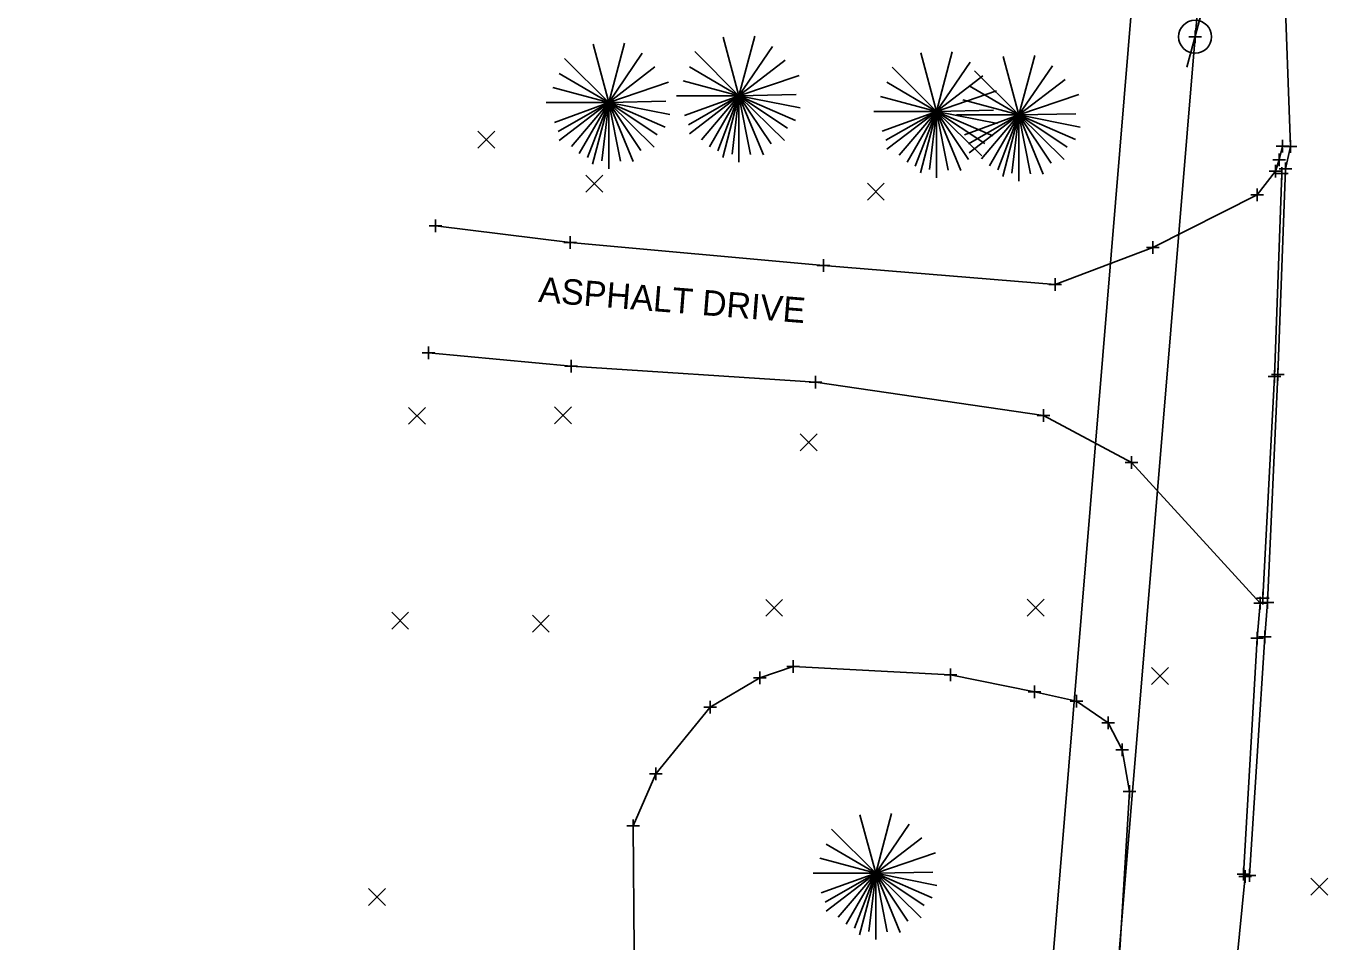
# Model space of a CAD drawing. Extents: x 1380440 to 1381945, y 468756 to 470369.
# Drawn here: x 1381467.5 to 1381570.5, y 469686 to 469758.2 of the extents above; entities that cross this region are included whole.
import ezdxf

# ---------------------------------------------------------------- set-up
doc = ezdxf.new("R2010")
doc.units = 0
for name, color, linetype in [('DR_P_Storm_Sewer', 7, 'Continuous'), ('DR_X_Cells', 7, 'Continuous'), ('GE_P_Driveway_CL', 7, 'Continuous'), ('PV_X_COP', 7, 'Continuous'), ('RW_P_Esmt_TMP', 7, 'Continuous'), ('RW_X_Esmt_SH', 7, 'Continuous'), ('SC_Scratch10', 7, 'Continuous'), ('SH_Named_Boundary', 7, 'Continuous'), ('UT_X_Gas', 7, 'Continuous'), ('UT_X_Overhead_Combined', 7, 'Continuous'), ('X-SUBDIVISION', 7, 'Continuous')]:
    doc.layers.add(name, color=color, linetype=linetype)

msp = doc.modelspace()

# ---------------------------------------------------------------- linework, layer by layer
at = {"layer": 'DR_P_Storm_Sewer'}
msp.add_lwpolyline([(1381553.61, 469681.87), (1381554.59, 469697.85), (1381554.02, 469701.13), (1381552.9, 469703.26), (1381550.42, 469704.97), (1381547.1, 469705.7), (1381540.46, 469707.05), (1381528.05, 469707.71), (1381525.41, 469706.81), (1381521.51, 469704.5), (1381517.2, 469699.24), (1381515.42, 469695.13), (1381515.51, 469685.3), (1381518.45, 469671.91), (1381521.91, 469663.58), (1381525.51, 469660.65), (1381530.1, 469658.77), (1381537.53, 469659.25), (1381542.81, 469659.47), (1381547.18, 469661.79), (1381552.24, 469676.73)], close=True, dxfattribs=at)
at = {"layer": 'DR_X_Cells'}
for points in [[(1381566.66, 469748.77), (1381566.42, 469747.7), (1381566.12, 469746.81)], [(1381564.9, 469712.7), (1381564.68, 469709.94), (1381563.59, 469691.32)]]:
    msp.add_lwpolyline(points, dxfattribs=at)
at = {"layer": 'GE_P_Driveway_CL'}
for p, q in [((1381503.17, 469748.62), (1381504.5, 469749.95)), ((1381503.17, 469749.95), (1381504.5, 469748.62)), ((1381511.69, 469745.13), (1381513.02, 469746.47)), ((1381511.69, 469746.47), (1381513.02, 469745.13)), ((1381533.91, 469744.5), (1381535.24, 469745.84)), ((1381533.91, 469745.84), (1381535.24, 469744.5)), ((1381497.68, 469726.82), (1381499.02, 469728.15)), ((1381497.68, 469728.15), (1381499.02, 469726.82)), ((1381509.22, 469726.87), (1381510.55, 469728.2)), ((1381509.22, 469728.2), (1381510.55, 469726.87)), ((1381528.6, 469724.74), (1381529.94, 469726.07)), ((1381528.6, 469726.07), (1381529.94, 469724.74)), ((1381525.88, 469711.67), (1381527.21, 469713)), ((1381525.88, 469713), (1381527.21, 469711.67)), ((1381546.53, 469711.69), (1381547.86, 469713.03)), ((1381546.53, 469713.03), (1381547.86, 469711.69)), ((1381496.37, 469710.66), (1381497.7, 469711.99)), ((1381496.37, 469711.99), (1381497.7, 469710.66)), ((1381507.47, 469710.43), (1381508.8, 469711.77)), ((1381507.47, 469711.77), (1381508.8, 469710.43)), ((1381556.34, 469706.3), (1381557.67, 469707.64)), ((1381556.34, 469707.64), (1381557.67, 469706.3)), ((1381494.53, 469688.85), (1381495.87, 469690.18)), ((1381494.53, 469690.18), (1381495.87, 469688.85)), ((1381568.91, 469689.67), (1381570.25, 469691.01)), ((1381568.91, 469691.01), (1381570.25, 469689.67))]:
    msp.add_line(p, q, dxfattribs=at)
at = {"layer": 'PV_X_COP'}
msp.add_line((1381560.74, 469761.01), (1381559.13, 469755.01), dxfattribs=at)
msp.add_circle((1381559.77, 469757.41), 1.3, dxfattribs=at)
at = {"layer": 'RW_P_Esmt_TMP'}
msp.add_lwpolyline([(1381504.03, 469796.45), (1381535.81, 469794.23), (1381542.35, 469793.56), (1381553.91, 469786.69), (1381557.54, 469783.33), (1381558.31, 469783.03), (1381558.93, 469783.94), (1381560.15, 469782.7), (1381561.95, 469780.57), (1381562.88, 469779.33), (1381563.72, 469777.65), (1381566.46, 469770.89), (1381567.07, 469765.6), (1381567.32, 469762.48), (1381566.8, 469762.44), (1381567.31, 469748.74), (1381566.9, 469746.97), (1381566.29, 469730.74), (1381565.48, 469712.75), (1381565.27, 469710.06), (1381564.07, 469691.21), (1381563.72, 469691.13), (1381563.05, 469684.22)], dxfattribs=at)
at = {"layer": 'RW_X_Esmt_SH'}
for points in [[(1381566.12, 469746.81), (1381564.67, 469744.93), (1381556.43, 469740.78), (1381548.72, 469737.86), (1381530.45, 469739.35), (1381510.46, 469741.16), (1381499.82, 469742.49)], [(1381566.61, 469746.61), (1381566.05, 469730.59), (1381565.13, 469713.09)], [(1381499.26, 469732.46), (1381510.53, 469731.41), (1381529.82, 469730.14), (1381547.8, 469727.52), (1381554.75, 469723.81), (1381564.9, 469712.7)]]:
    msp.add_lwpolyline(points, dxfattribs=at)
at = {"layer": 'SC_Scratch10'}
for p, q in [((1381523.77, 469752.75), (1381522.53, 469757.36)), ((1381523.77, 469752.75), (1381525.03, 469757.44)), ((1381513.49, 469752.21), (1381512.25, 469756.83)), ((1381513.49, 469752.21), (1381514.74, 469756.91)), ((1381513.49, 469752.21), (1381516.14, 469756.1)), ((1381523.77, 469752.75), (1381520.28, 469756.23)), ((1381523.77, 469752.75), (1381526.42, 469756.63)), ((1381539.35, 469751.52), (1381538.12, 469756.13)), ((1381539.35, 469751.52), (1381540.61, 469756.22)), ((1381545.86, 469751.24), (1381547.12, 469755.93)), ((1381513.49, 469752.21), (1381510, 469755.7)), ((1381513.49, 469752.21), (1381517.14, 469755.02)), ((1381523.77, 469752.75), (1381519.86, 469755.04)), ((1381523.77, 469752.75), (1381527.43, 469755.55)), ((1381539.35, 469751.52), (1381535.86, 469755.01)), ((1381539.35, 469751.52), (1381542.01, 469755.41)), ((1381545.86, 469751.24), (1381544.62, 469755.85)), ((1381545.86, 469751.24), (1381548.51, 469755.12)), ((1381513.49, 469752.21), (1381509.58, 469754.51)), ((1381523.77, 469752.75), (1381519.36, 469753.93)), ((1381523.77, 469752.75), (1381528.51, 469754.35)), ((1381539.35, 469751.52), (1381543.01, 469754.33)), ((1381545.86, 469751.24), (1381542.37, 469754.72)), ((1381545.86, 469751.24), (1381549.52, 469754.04)), ((1381513.49, 469752.21), (1381509.07, 469753.4)), ((1381513.49, 469752.21), (1381518.22, 469753.82)), ((1381523.77, 469752.75), (1381528.28, 469752.84)), ((1381539.35, 469751.52), (1381535.45, 469753.82)), ((1381539.35, 469751.52), (1381544.09, 469753.13)), ((1381545.86, 469751.24), (1381541.95, 469753.53)), ((1381545.86, 469751.24), (1381550.6, 469752.84)), ((1381508.55, 469752.21), (1381513.49, 469752.21)), ((1381513.49, 469752.21), (1381509.2, 469750.65)), ((1381513.49, 469752.21), (1381509.5, 469749.93)), ((1381513.49, 469752.21), (1381509.58, 469749.22)), ((1381513.49, 469752.21), (1381510.54, 469748.75)), ((1381513.49, 469752.21), (1381511.17, 469748.2)), ((1381513.49, 469752.21), (1381511.82, 469747.87)), ((1381513.49, 469752.21), (1381512.22, 469747.36)), ((1381513.49, 469752.21), (1381512.95, 469747.62)), ((1381513.49, 469752.21), (1381518, 469752.31)), ((1381513.49, 469746.97), (1381513.49, 469752.21)), ((1381513.49, 469752.21), (1381514.41, 469747.58)), ((1381513.49, 469752.21), (1381515.42, 469747.55)), ((1381513.49, 469752.21), (1381516.02, 469748.42)), ((1381513.49, 469752.21), (1381517.08, 469748.69)), ((1381513.49, 469752.21), (1381517.31, 469749.66)), ((1381513.49, 469752.21), (1381517.95, 469750.27)), ((1381513.49, 469752.21), (1381518.32, 469751.26)), ((1381518.83, 469752.75), (1381523.77, 469752.75)), ((1381523.77, 469752.75), (1381519.48, 469751.18)), ((1381523.77, 469752.75), (1381519.79, 469750.46)), ((1381523.77, 469752.75), (1381519.86, 469749.75)), ((1381523.77, 469752.75), (1381520.82, 469749.28)), ((1381523.77, 469752.75), (1381521.45, 469748.73)), ((1381523.77, 469752.75), (1381522.1, 469748.41)), ((1381523.77, 469752.75), (1381522.51, 469747.89)), ((1381523.77, 469752.75), (1381523.23, 469748.15)), ((1381523.77, 469747.51), (1381523.77, 469752.75)), ((1381523.77, 469752.75), (1381524.69, 469748.11)), ((1381523.77, 469752.75), (1381525.7, 469748.08)), ((1381523.77, 469752.75), (1381526.31, 469748.95)), ((1381523.77, 469752.75), (1381527.36, 469749.22)), ((1381523.77, 469752.75), (1381527.59, 469750.19)), ((1381523.77, 469752.75), (1381528.23, 469750.8)), ((1381523.77, 469752.75), (1381528.6, 469751.79)), ((1381539.35, 469751.52), (1381534.94, 469752.7)), ((1381545.86, 469751.24), (1381541.45, 469752.42)), ((1381534.42, 469751.52), (1381539.35, 469751.52)), ((1381539.35, 469751.52), (1381535.06, 469749.96)), ((1381539.35, 469751.52), (1381535.37, 469749.24)), ((1381539.35, 469751.52), (1381535.45, 469748.53)), ((1381539.35, 469751.52), (1381536.41, 469748.05)), ((1381539.35, 469751.52), (1381537.04, 469747.51)), ((1381539.35, 469751.52), (1381537.69, 469747.18)), ((1381539.35, 469751.52), (1381538.09, 469746.66)), ((1381539.35, 469751.52), (1381538.81, 469746.93)), ((1381539.35, 469751.52), (1381543.86, 469751.61)), ((1381539.35, 469746.28), (1381539.35, 469751.52)), ((1381539.35, 469751.52), (1381540.28, 469746.88)), ((1381539.35, 469751.52), (1381541.29, 469746.85)), ((1381539.35, 469751.52), (1381541.89, 469747.73)), ((1381539.35, 469751.52), (1381542.94, 469748)), ((1381539.35, 469751.52), (1381543.18, 469748.97)), ((1381539.35, 469751.52), (1381543.82, 469749.58)), ((1381539.35, 469751.52), (1381544.18, 469750.56)), ((1381540.93, 469751.24), (1381545.86, 469751.24)), ((1381545.86, 469751.24), (1381541.57, 469749.67)), ((1381545.86, 469751.24), (1381541.88, 469748.95)), ((1381545.86, 469751.24), (1381541.95, 469748.24)), ((1381545.86, 469751.24), (1381542.92, 469747.77)), ((1381545.86, 469751.24), (1381543.54, 469747.22)), ((1381545.86, 469751.24), (1381544.2, 469746.9)), ((1381545.86, 469751.24), (1381544.6, 469746.38)), ((1381545.86, 469751.24), (1381545.32, 469746.64)), ((1381545.86, 469751.24), (1381550.37, 469751.33)), ((1381545.86, 469746), (1381545.86, 469751.24)), ((1381545.86, 469751.24), (1381546.78, 469746.6)), ((1381545.86, 469751.24), (1381547.79, 469746.57)), ((1381545.86, 469751.24), (1381548.4, 469747.44)), ((1381545.86, 469751.24), (1381549.45, 469747.71)), ((1381545.86, 469751.24), (1381549.68, 469748.68)), ((1381545.86, 469751.24), (1381550.32, 469749.29)), ((1381545.86, 469751.24), (1381550.69, 469750.28)), ((1381534.56, 469691.4), (1381533.32, 469696.01)), ((1381534.56, 469691.4), (1381535.81, 469696.1)), ((1381534.56, 469691.4), (1381537.21, 469695.28)), ((1381534.56, 469691.4), (1381531.07, 469694.88)), ((1381534.56, 469691.4), (1381538.21, 469694.2)), ((1381534.56, 469691.4), (1381530.65, 469693.69)), ((1381534.56, 469691.4), (1381530.14, 469692.58)), ((1381534.56, 469691.4), (1381539.29, 469693)), ((1381529.62, 469691.4), (1381534.56, 469691.4)), ((1381534.56, 469691.4), (1381530.27, 469689.84)), ((1381534.56, 469691.4), (1381530.57, 469689.12)), ((1381534.56, 469691.4), (1381530.65, 469688.4)), ((1381534.56, 469691.4), (1381531.61, 469687.93)), ((1381534.56, 469691.4), (1381532.24, 469687.38)), ((1381534.56, 469691.4), (1381532.89, 469687.06)), ((1381534.56, 469691.4), (1381533.29, 469686.54)), ((1381534.56, 469691.4), (1381534.01, 469686.81)), ((1381534.56, 469691.4), (1381539.07, 469691.49)), ((1381534.56, 469686.16), (1381534.56, 469691.4)), ((1381534.56, 469691.4), (1381535.48, 469686.76)), ((1381534.56, 469691.4), (1381536.49, 469686.73)), ((1381534.56, 469691.4), (1381537.09, 469687.6)), ((1381534.56, 469691.4), (1381538.14, 469687.88)), ((1381534.56, 469691.4), (1381538.38, 469688.84)), ((1381534.56, 469691.4), (1381539.02, 469689.46)), ((1381534.56, 469691.4), (1381539.38, 469690.44))]:
    msp.add_line(p, q, dxfattribs=at)
at = {"layer": 'SH_Named_Boundary'}
for p, q in [((1381559.27, 469757.41), (1381560.27, 469757.41)), ((1381559.27, 469757.41), (1381560.27, 469757.41)), ((1381559.77, 469757.91), (1381559.77, 469756.91)), ((1381559.77, 469757.91), (1381559.77, 469756.91)), ((1381559.77, 469757.41), (1381559.77, 469757.41)), ((1381559.77, 469757.41), (1381559.77, 469757.41)), ((1381566.16, 469748.77), (1381567.16, 469748.77)), ((1381566.66, 469749.27), (1381566.66, 469748.27)), ((1381566.66, 469748.77), (1381566.66, 469748.77)), ((1381566.81, 469748.74), (1381567.81, 469748.74)), ((1381567.31, 469749.24), (1381567.31, 469748.24)), ((1381567.31, 469748.74), (1381567.31, 469748.74)), ((1381565.92, 469747.7), (1381566.92, 469747.7)), ((1381566.42, 469748.2), (1381566.42, 469747.2)), ((1381566.42, 469747.7), (1381566.42, 469747.7)), ((1381565.62, 469746.81), (1381566.62, 469746.81)), ((1381565.62, 469746.81), (1381566.62, 469746.81)), ((1381566.12, 469747.31), (1381566.12, 469746.31)), ((1381566.12, 469747.31), (1381566.12, 469746.31)), ((1381566.12, 469746.81), (1381566.12, 469746.81)), ((1381566.12, 469746.81), (1381566.12, 469746.81)), ((1381566.4, 469746.97), (1381567.4, 469746.97)), ((1381566.61, 469747.11), (1381566.61, 469746.11)), ((1381566.9, 469747.47), (1381566.9, 469746.47)), ((1381566.9, 469746.97), (1381566.9, 469746.97)), ((1381566.11, 469746.61), (1381567.11, 469746.61)), ((1381566.61, 469746.61), (1381566.61, 469746.61)), ((1381564.17, 469744.93), (1381565.17, 469744.93)), ((1381564.17, 469744.93), (1381565.17, 469744.93)), ((1381564.67, 469745.43), (1381564.67, 469744.43)), ((1381564.67, 469745.43), (1381564.67, 469744.43)), ((1381564.67, 469744.93), (1381564.67, 469744.93)), ((1381564.67, 469744.93), (1381564.67, 469744.93)), ((1381499.82, 469742.99), (1381499.82, 469741.99)), ((1381499.32, 469742.49), (1381500.32, 469742.49)), ((1381499.82, 469742.49), (1381499.82, 469742.49)), ((1381510.46, 469741.66), (1381510.46, 469740.66)), ((1381509.96, 469741.16), (1381510.96, 469741.16)), ((1381510.46, 469741.16), (1381510.46, 469741.16)), ((1381555.93, 469740.78), (1381556.93, 469740.78)), ((1381556.43, 469741.28), (1381556.43, 469740.28)), ((1381556.43, 469740.78), (1381556.43, 469740.78)), ((1381530.45, 469739.85), (1381530.45, 469738.85)), ((1381529.95, 469739.35), (1381530.95, 469739.35)), ((1381530.45, 469739.35), (1381530.45, 469739.35)), ((1381548.22, 469737.86), (1381549.22, 469737.86)), ((1381548.22, 469737.86), (1381549.22, 469737.86)), ((1381548.72, 469738.36), (1381548.72, 469737.36)), ((1381548.72, 469738.36), (1381548.72, 469737.36)), ((1381548.72, 469737.86), (1381548.72, 469737.86)), ((1381548.72, 469737.86), (1381548.72, 469737.86)), ((1381498.76, 469732.46), (1381499.76, 469732.46)), ((1381499.26, 469732.96), (1381499.26, 469731.96)), ((1381499.26, 469732.46), (1381499.26, 469732.46)), ((1381510.03, 469731.41), (1381511.03, 469731.41)), ((1381510.53, 469731.91), (1381510.53, 469730.91)), ((1381510.53, 469731.41), (1381510.53, 469731.41)), ((1381566.29, 469731.24), (1381566.29, 469730.24)), ((1381529.82, 469730.64), (1381529.82, 469729.64)), ((1381565.55, 469730.59), (1381566.55, 469730.59)), ((1381565.79, 469730.74), (1381566.79, 469730.74)), ((1381566.05, 469731.09), (1381566.05, 469730.09)), ((1381566.05, 469730.59), (1381566.05, 469730.59)), ((1381566.29, 469730.74), (1381566.29, 469730.74)), ((1381529.32, 469730.14), (1381530.32, 469730.14)), ((1381529.82, 469730.14), (1381529.82, 469730.14)), ((1381547.3, 469727.52), (1381548.3, 469727.52)), ((1381547.8, 469728.02), (1381547.8, 469727.02)), ((1381547.8, 469727.52), (1381547.8, 469727.52)), ((1381554.75, 469724.31), (1381554.75, 469723.31)), ((1381554.25, 469723.81), (1381555.25, 469723.81)), ((1381554.75, 469723.81), (1381554.75, 469723.81)), ((1381564.4, 469712.7), (1381565.4, 469712.7)), ((1381564.4, 469712.7), (1381565.4, 469712.7)), ((1381564.63, 469713.09), (1381565.63, 469713.09)), ((1381564.9, 469713.2), (1381564.9, 469712.2)), ((1381564.9, 469713.2), (1381564.9, 469712.2)), ((1381564.9, 469712.7), (1381564.9, 469712.7)), ((1381564.9, 469712.7), (1381564.9, 469712.7)), ((1381564.98, 469712.75), (1381565.98, 469712.75)), ((1381565.13, 469713.59), (1381565.13, 469712.59)), ((1381565.13, 469713.09), (1381565.13, 469713.09)), ((1381565.48, 469713.25), (1381565.48, 469712.25)), ((1381565.48, 469712.75), (1381565.48, 469712.75)), ((1381564.18, 469709.94), (1381565.18, 469709.94)), ((1381564.68, 469710.44), (1381564.68, 469709.44)), ((1381564.68, 469709.94), (1381564.68, 469709.94)), ((1381564.77, 469710.06), (1381565.77, 469710.06)), ((1381565.27, 469710.56), (1381565.27, 469709.56)), ((1381565.27, 469710.06), (1381565.27, 469710.06)), ((1381527.55, 469707.71), (1381528.55, 469707.71)), ((1381528.05, 469708.21), (1381528.05, 469707.21)), ((1381528.05, 469707.71), (1381528.05, 469707.71)), ((1381540.46, 469707.55), (1381540.46, 469706.55)), ((1381524.91, 469706.81), (1381525.91, 469706.81)), ((1381525.41, 469707.31), (1381525.41, 469706.31)), ((1381525.41, 469706.81), (1381525.41, 469706.81)), ((1381539.96, 469707.05), (1381540.96, 469707.05)), ((1381540.46, 469707.05), (1381540.46, 469707.05)), ((1381546.6, 469705.7), (1381547.6, 469705.7)), ((1381547.1, 469706.2), (1381547.1, 469705.2)), ((1381547.1, 469705.7), (1381547.1, 469705.7)), ((1381550.42, 469705.47), (1381550.42, 469704.47)), ((1381521.01, 469704.5), (1381522.01, 469704.5)), ((1381521.51, 469705), (1381521.51, 469704)), ((1381521.51, 469704.5), (1381521.51, 469704.5)), ((1381549.92, 469704.97), (1381550.92, 469704.97)), ((1381550.42, 469704.97), (1381550.42, 469704.97)), ((1381552.9, 469703.76), (1381552.9, 469702.76)), ((1381552.4, 469703.26), (1381553.4, 469703.26)), ((1381552.9, 469703.26), (1381552.9, 469703.26)), ((1381554.02, 469701.63), (1381554.02, 469700.63)), ((1381553.52, 469701.13), (1381554.52, 469701.13)), ((1381554.02, 469701.13), (1381554.02, 469701.13)), ((1381517.2, 469699.74), (1381517.2, 469698.74)), ((1381516.7, 469699.24), (1381517.7, 469699.24)), ((1381517.2, 469699.24), (1381517.2, 469699.24)), ((1381554.59, 469698.35), (1381554.59, 469697.35)), ((1381554.09, 469697.85), (1381555.09, 469697.85)), ((1381554.59, 469697.85), (1381554.59, 469697.85)), ((1381515.42, 469695.63), (1381515.42, 469694.63)), ((1381514.92, 469695.13), (1381515.92, 469695.13)), ((1381515.42, 469695.13), (1381515.42, 469695.13)), ((1381563.09, 469691.32), (1381564.09, 469691.32)), ((1381563.22, 469691.13), (1381564.22, 469691.13)), ((1381563.57, 469691.21), (1381564.57, 469691.21)), ((1381563.59, 469691.82), (1381563.59, 469690.82)), ((1381563.59, 469691.32), (1381563.59, 469691.32)), ((1381563.72, 469691.63), (1381563.72, 469690.63)), ((1381563.72, 469691.13), (1381563.72, 469691.13)), ((1381564.07, 469691.71), (1381564.07, 469690.71)), ((1381564.07, 469691.21), (1381564.07, 469691.21))]:
    msp.add_line(p, q, dxfattribs=at)
at = {"layer": 'UT_X_Gas'}
msp.add_lwpolyline([(1381485.9, 468926.41), (1381594.27, 470237.89), (1380558, 470279.29)], dxfattribs=at)
at = {"layer": 'UT_X_Overhead_Combined'}
msp.add_lwpolyline([(1381540.8, 469054.26), (1381515.28, 469203.1), (1381529.17, 469390.12), (1381543.86, 469565.78), (1381559.77, 469757.41), (1381571.97, 469887.64), (1381581.26, 470018.2), (1381595.79, 470220.83), (1381665.56, 470247.4)], dxfattribs=at)

# ---------------------------------------------------------------- texts
at = {"layer": 'X-SUBDIVISION'}
msp.add_text('ASPHALT DRIVE', height=2, rotation=355.4428, dxfattribs=at).set_placement((1381507.9, 469736.48))

doc.saveas('drawing.dxf')
